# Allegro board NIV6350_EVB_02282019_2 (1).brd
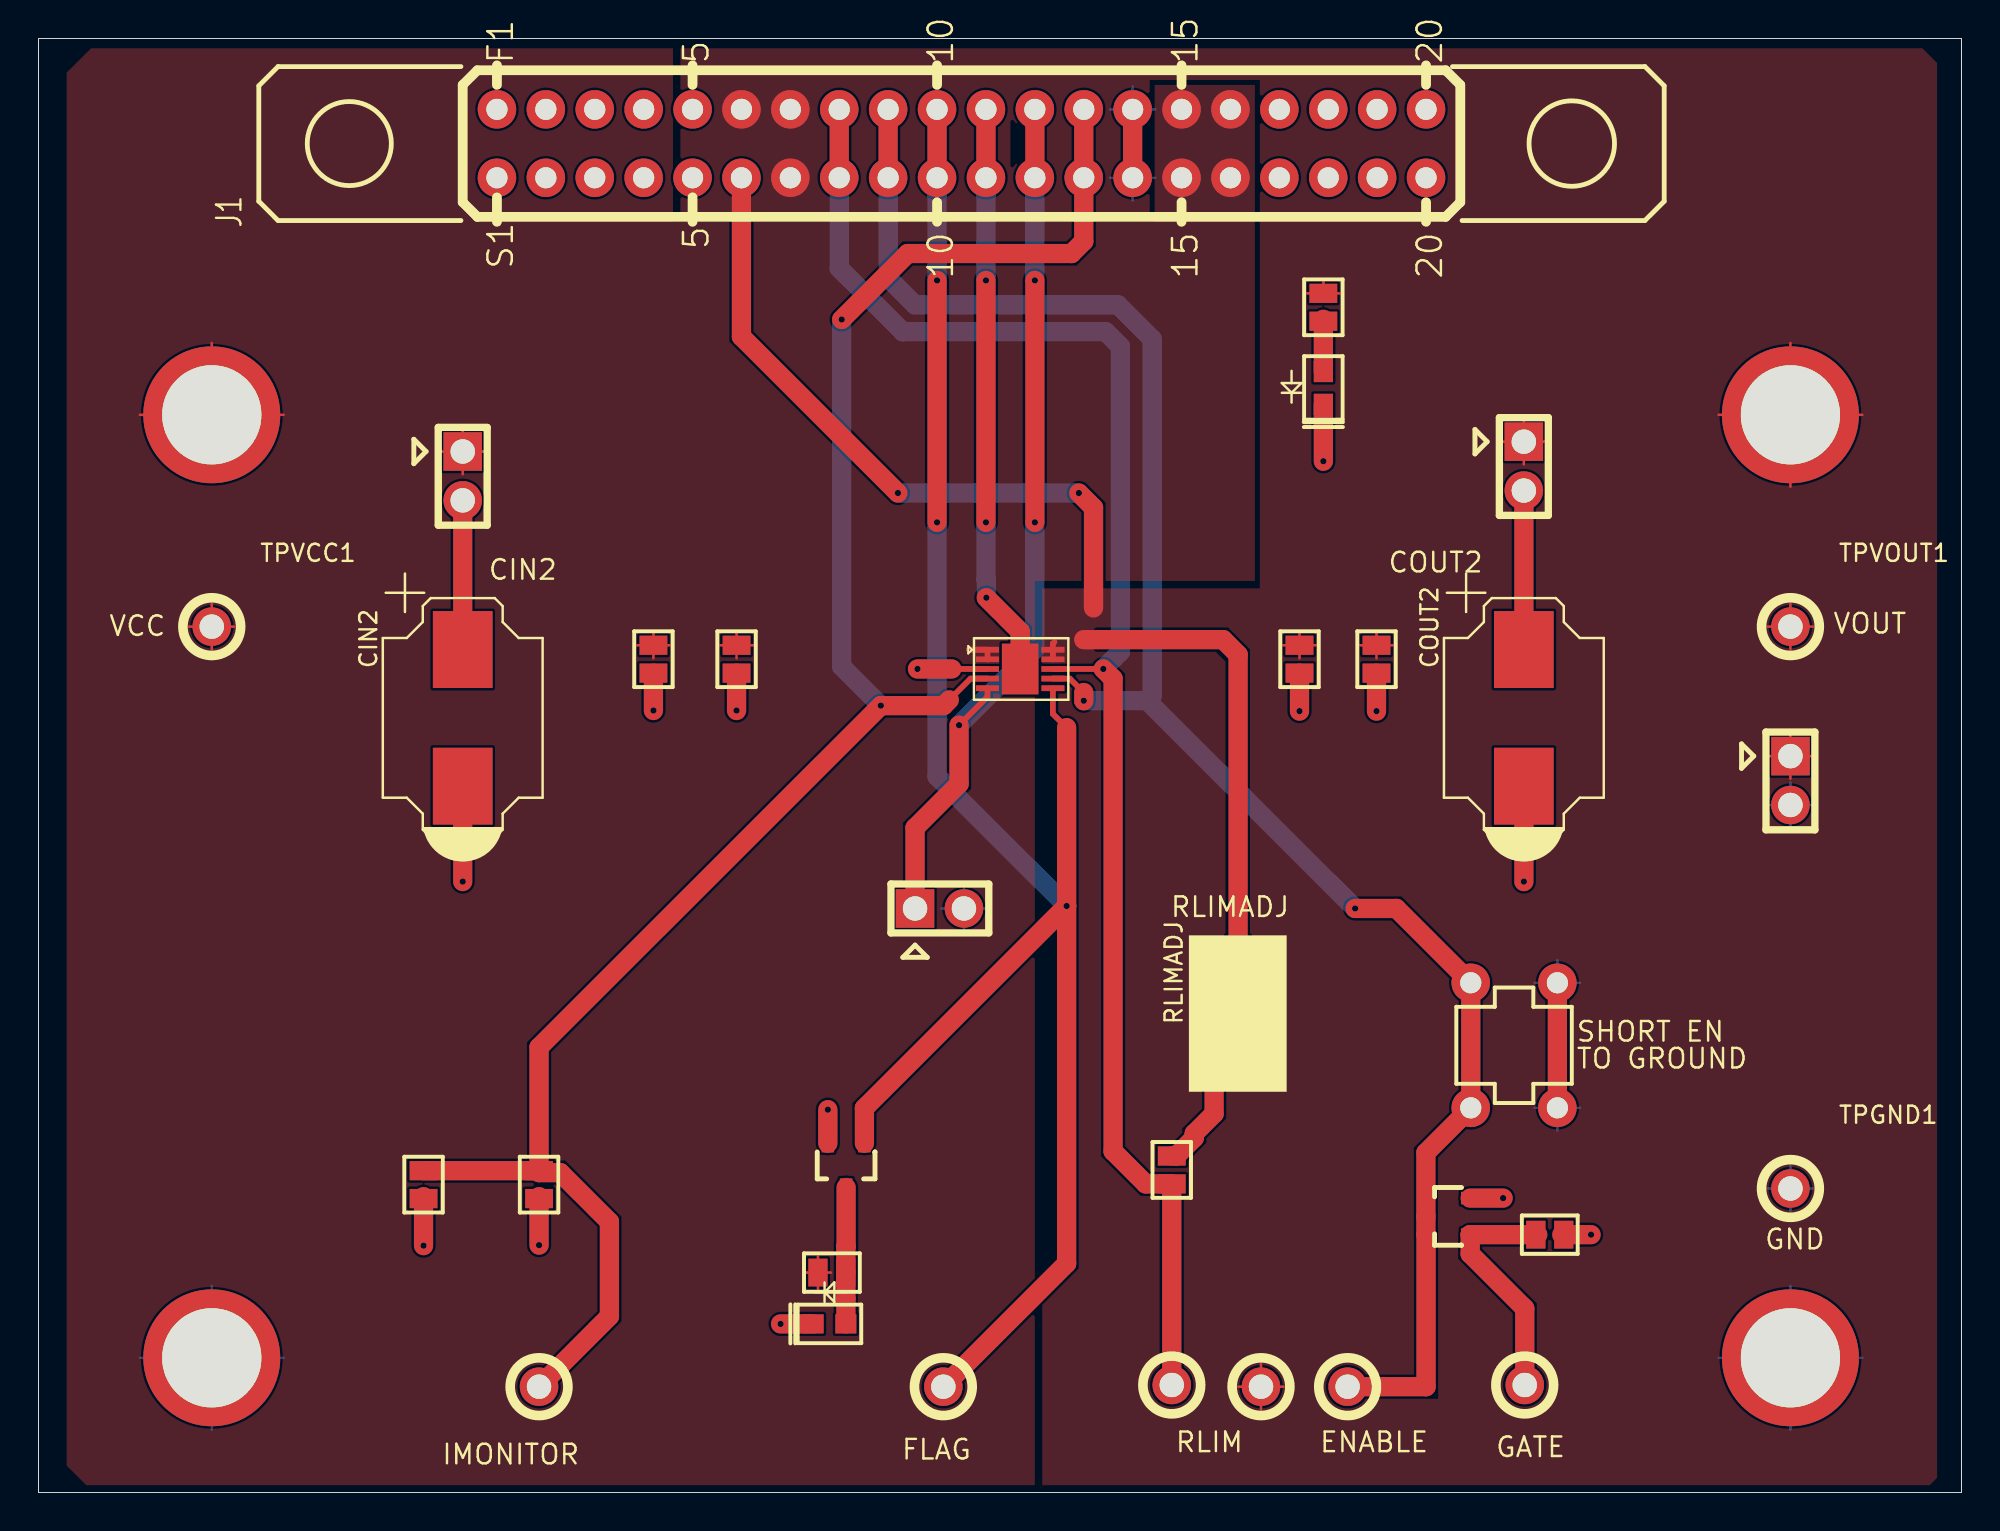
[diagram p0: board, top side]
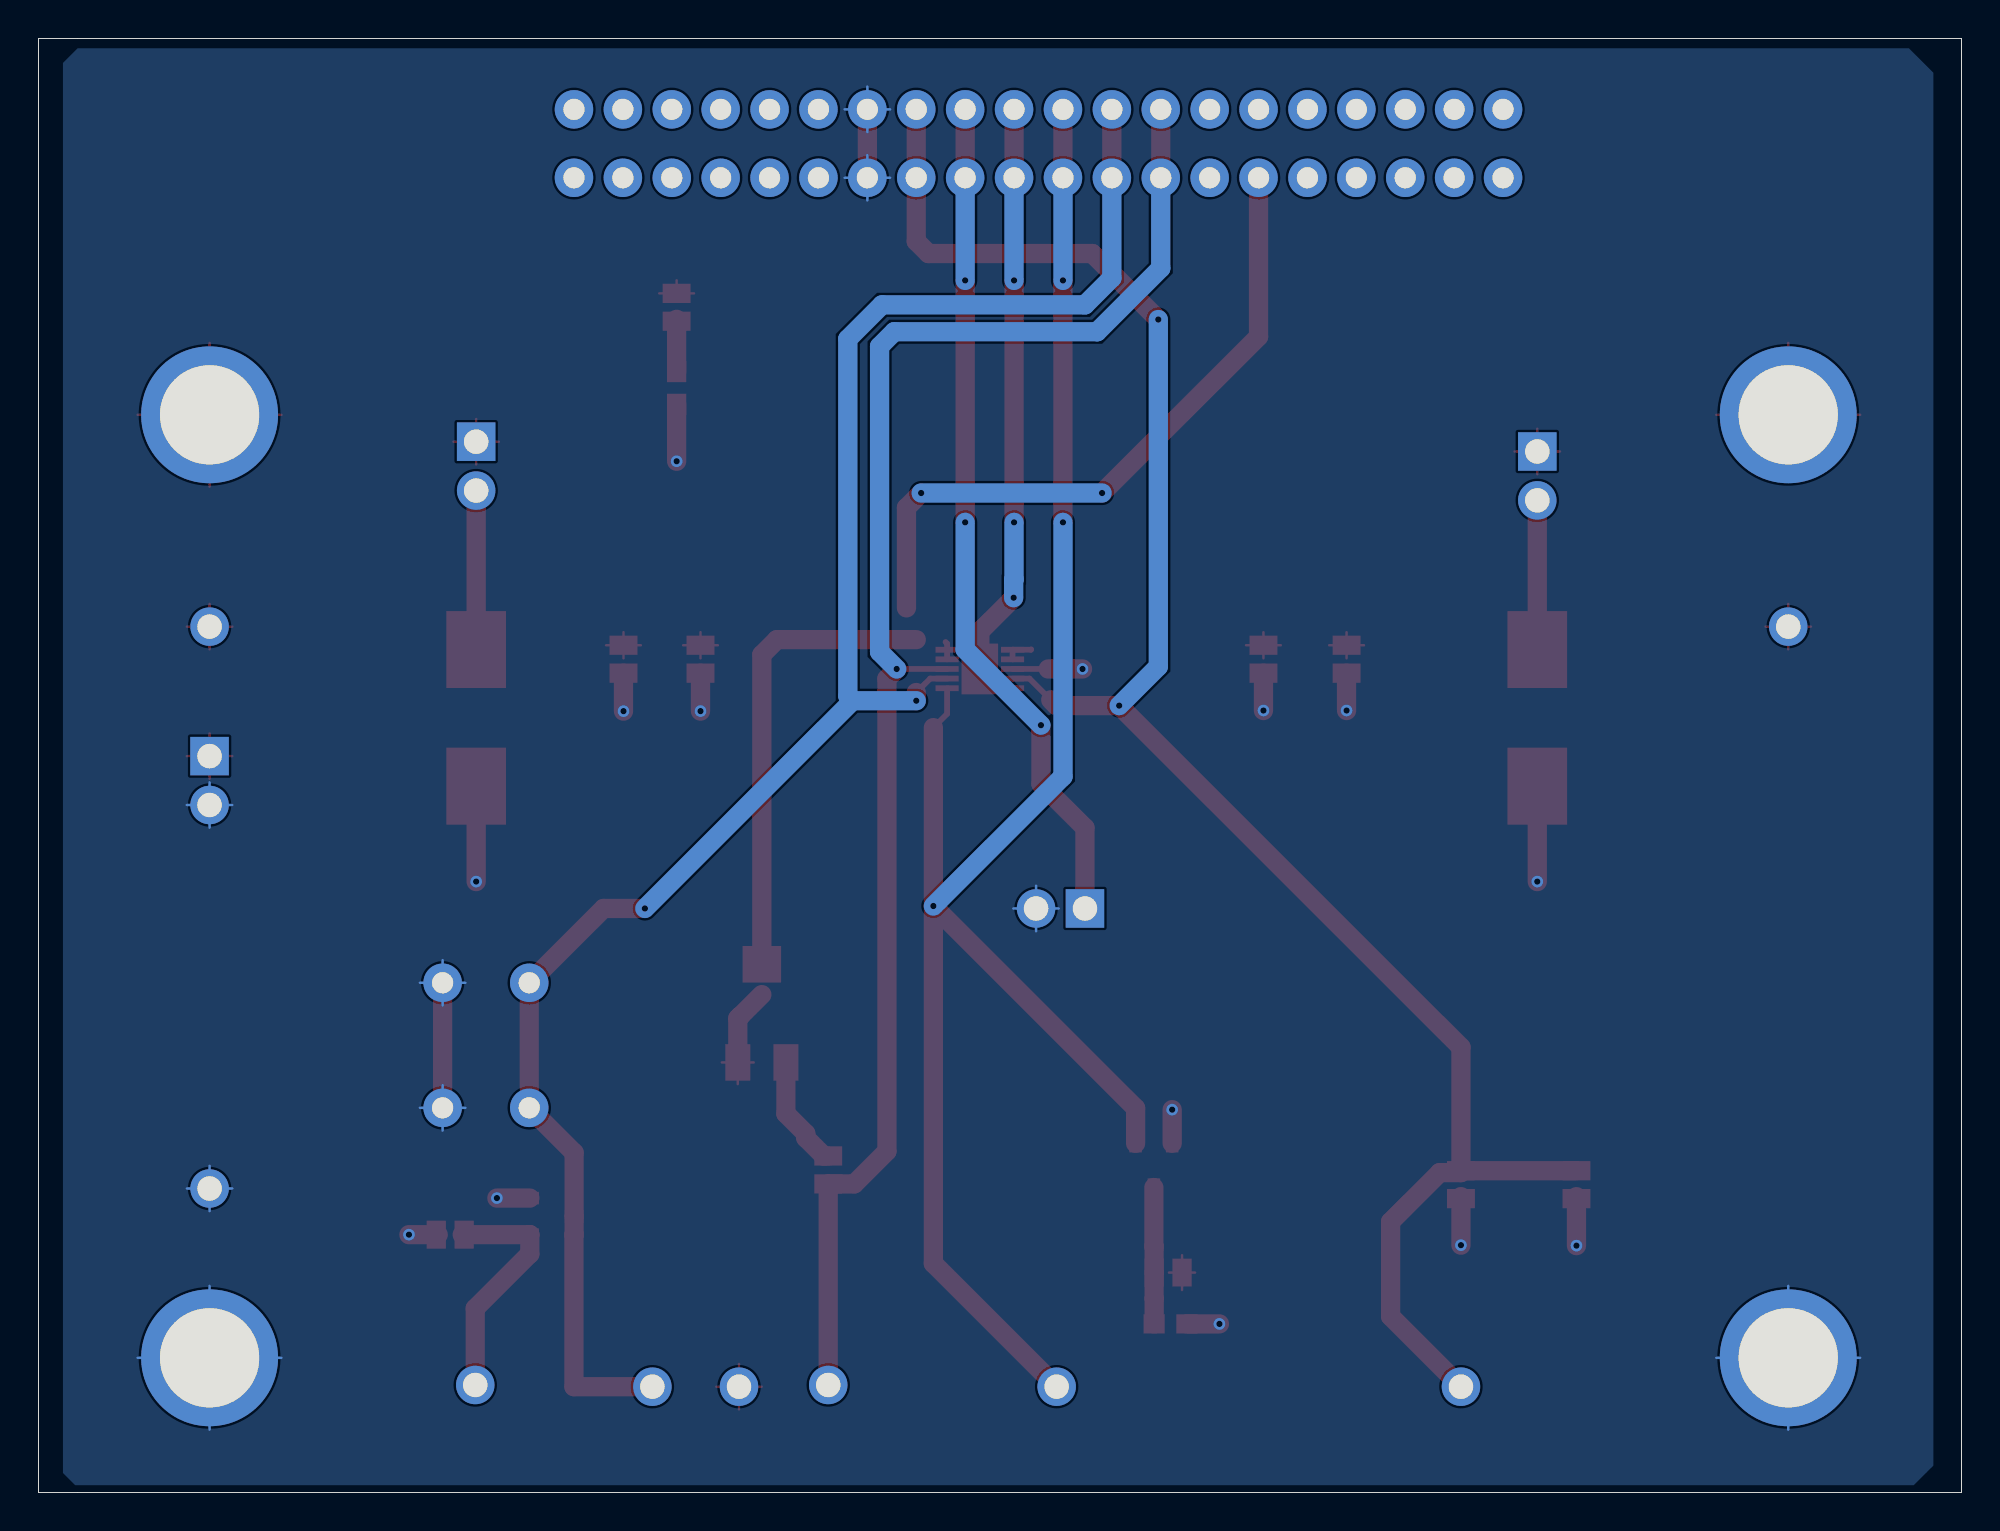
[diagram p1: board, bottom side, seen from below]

Outline 99.89 x 75.56 mm; copper layers: TOP, BOTTOM. Coordinates in mm from the lower left corner of the outline.
Outline path: 0,75.56 99.89,75.56 99.89,0 0,0 0,75.56

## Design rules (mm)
constraint set DEFAULT: min track width 0.127

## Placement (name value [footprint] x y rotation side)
CIMON  1 uF/50V  [0805]  26 16 270 top
CIN1  1uF/50V  [0805]  36.26 43.31 270 top
CIN2  56u/35V  [CAP_SMD_8P3X8P3]  22.04 40.26 90 top
COUT1  1uF/50V  [0805]  65.5 43.31 270 top
COUT2  56uF/35V  [CAP_SMD_8P3X8P3]  77.15 40.26 90 top
D1  LED0603-YELLOW  [LED0603]  41.09 8.76 180 top
EN_SW  PB-SW  [SW-TAC-SPST]  76.64 23.24 90 top
J1  CON40  [ABC20DRT]  47.94 70.1 90 top
J2  TP  [TP-HOOK]  68 5.5 0 top
J3  TP  [TP-HOOK]  47 5.5 0 top
J5  TP  [TP-HOOK]  77.2 5.59 0 top
J_VC_SEL  HDR2  [HEADER-2]  46.8 30.35 0 top
JCIN2  HDR-2  [HEADER-2]  22.04 52.83 270 top
JCOUT2  HDR-2  [HEADER-2]  77.15 53.34 270 top
JGND1  BANANA JACK  [BANANA_VIA]  9 7 0 top
JGND2  BANANA JACK  [BANANA_VIA]  91 7 0 top
JOUTPUTSHORT  HDR-2  [HEADER-2]  91 37 270 top
JVCC1  BANANA JACK  [BANANA_VIA]  9 56.01 0 top
JVOUT1  BANANA JACK  [BANANA_VIA]  91 56.01 0 top
LEDOUT  LED0603-GREEN  [LED0603]  66.74 57.4 270 top
M1  2N7002KT1G  [SOT-23]  73.22 14.35 180 top
M2  2N7002KT1G  [SOT-23]  41.95 17 270 top
R1  10K  [0805]  78.5 13.4 0 top
R2  RFaultLED  [0805]  41.21 11.43 0 top
RIMON  1k  [0805]  20 16 270 top
RLEDOUT  10K  [0805]  66.74 61.59 270 top
RLIMADJ  100  [3214X_TRIM_POT]  63.56 22.35 90 top
RLIMMIN  1  [0805]  58.87 16.76 270 top
TPGND1  -  [TP-HOOK]  91 15.8 0 top
TPIMON  -  [TP-HOOK]  26 5.5 0 top
TPRLIM1  -  [TP-HOOK]  58.87 5.59 0 top
TPRLIM2  -  [TP-HOOK]  63.5 5.5 0 top
TPVCC1  -  [TP-HOOK]  9 45 0 top
TPVOUT1  -  [TP-HOOK]  91 45 0 top
U1  NIV6350  [DFN-10-3X3-05MM]  50.99 42.8 270 top
ZDIN  DIODE ZENER  [0805]  31.94 43.31 270 top
ZDOUT  DIODE ZENER  [0805]  69.5 43.31 270 top

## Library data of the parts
CIMON CIN1 COUT1 = CAP NP
CIN2 COUT2 = CAP
D1 LEDOUT = LED_0
EN_SW = PUSH-BUTTON-SW_2: Tolerance: TOL; User Part Number: PN
J1 = CON40_0
J2 J3 J5 TPGND1 TPIMON TPRLIM1 TPRLIM2 TPVCC1 TPVOUT1 = TP-HOOK
J_VC_SEL = HEADER 2_0: User Part Number: PN; Tolerance: TOL
JCIN2 JCOUT2 JOUTPUTSHORT = HEADER 2_1: User Part Number: PN; Tolerance: TOL
JGND1 JGND2 JVCC1 JVOUT1 = Banana Conn
M1 M2 = MMDF4N01HD/ON_1: User Part Number: PN; Tolerance: TOL
R1 R2 RIMON RLEDOUT RLIMMIN = RESISTOR
RLIMADJ = POT/SM
U1 = NIV6350
ZDIN ZDOUT = DIODE ZENER

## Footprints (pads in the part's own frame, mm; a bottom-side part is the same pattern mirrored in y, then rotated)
0805
  rect 1x1.45 smd: 1(-0.725,0) 2(0.725,0)
3214X_TRIM_POT
  rect 1.9x1.3 smd: 1(0,0) 3(0,2.5)
  rect 1.9x2 smd: 2(5.1,1.25)
ABC20DRT
  round 2 hole 1.1: 1(-1.778,24.13) 2(1.778,24.13) 3(-1.778,21.59) 4(1.778,21.59) 5(-1.778,19.05) 6(1.778,19.05) 7(-1.778,16.51) 8(1.778,16.51) 9(-1.778,13.97) 10(1.778,13.97) 11(-1.778,11.43) 12(1.778,11.43) 13(-1.778,8.89) 14(1.778,8.89) 15(-1.778,6.35) 16(1.778,6.35) 17(-1.778,3.81) 18(1.778,3.81) 19(-1.778,1.27) 20(1.778,1.27) 21(-1.778,-1.27) 22(1.778,-1.27) 23(-1.778,-3.81) 24(1.778,-3.81) 25(-1.778,-6.35) 26(1.778,-6.35) 27(-1.778,-8.89) 28(1.778,-8.89) 29(-1.778,-11.43) 30(1.778,-11.43) 31(-1.778,-13.97) 32(1.778,-13.97) 33(-1.778,-16.51) 34(1.778,-16.51) 35(-1.778,-19.05) 36(1.778,-19.05) 37(-1.778,-21.59) 38(1.778,-21.59) 39(-1.778,-24.13) 40(1.778,-24.13)
BANANA_VIA
  round 7.112 hole 5.156: 1(0,0)
CAP_SMD_8P3X8P3
  rect 4x3.1 smd: 1(3.55,0) 2(-3.55,0)
DFN-10-3X3-05MM
  rect 0.3x1.2 smd: 1(-1,-1.7) 2(-0.5,-1.7) 3(0,-1.7) 4(0.5,-1.7) 5(1,-1.7) 6(1,1.7) 7(0.5,1.7) 8(0,1.7) 9(-0.5,1.7) 10(-1,1.7)
  rect 2.64x1.9 smd: 11(0,0)
HEADER-2
  rect 2x2 hole 1.27: 1(-1.27,0)
  round 2 hole 1.27: 2(1.27,0)
LED0603
  rect 1.1x1 smd: 1(0.851,0) 2(-0.851,0)
SOT-23
  rect 0.95x0.65 smd: 1(-1.15,0.95) 2(-1.15,-0.95) 3(1.15,0)
SW-TAC-SPST
  round 2 hole 1.1: 1(-3.25,-2.25) 2(3.25,-2.25) 3(-3.25,2.25) 4(3.25,2.25)
TP-HOOK
  round 2 hole 1.27: 1(0,0)

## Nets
GND: CIMON.2 CIN1.2 CIN2.2 COUT1.2 COUT2.2 D1.1(CATHODE) EN_SW.1 EN_SW.2 J1.27 J1.28 J_VC_SEL.2 JGND1.1 JGND2.1 JOUTPUTSHORT.2 LEDOUT.1(CATHODE) M1.2(S) M2.2(S) R1.2 RIMON.2 TPGND1.1 U1.3 ZDIN.2 ZDOUT.2
VCC: CIN1.1 J1.29 J1.30 J1.31 J1.32 JCIN2.1 JVCC1.1 R2.1 TPVCC1.1 U1.1 U1.2 ZDIN.1(CATHODE)
EN: EN_SW.3 EN_SW.4 J1.17 J1.18 J2.1 M1.3 U1.7
FLAG: J1.19 J1.20 J3.1 M2.1 U1.6
ILIM: J1.15 J1.16 RLIMMIN.2 TPRLIM1.1 U1.8
IMON: CIMON.1 J1.25 J1.26 RIMON.1 TPIMON.1 U1.4
TPAD: J1.21 J1.22 U1.11
VC_SEL: J1.23 J1.24 J_VC_SEL.1 U1.5(VC_SEL)
VSRC: COUT1.1 J1.11 J1.12 J1.13 J1.14 JCOUT2.1 JOUTPUTSHORT.1 JVOUT1.1 RLEDOUT.1 RLIMADJ.1 RLIMADJ.2(WIPER) TPRLIM2.1 TPVOUT1.1 U1.9 U1.10 ZDOUT.1(CATHODE)
N12391538: LEDOUT.2 RLEDOUT.2
N12393096: RLIMADJ.3 RLIMMIN.1
N14404692: COUT2.1 JCOUT2.2
N14450563: D1.2 M2.3 R2.2
N14454265: J5.1 M1.1 R1.1
N144197141: CIN2.1 JCIN2.2

Pads without a net: J1 1 2 3 4 5 6 7 8 9 10 33 34 35 36 37 38 39 40

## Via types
v1: diameter 0.61, hole 0.33, TOP to BOTTOM, 30 vias

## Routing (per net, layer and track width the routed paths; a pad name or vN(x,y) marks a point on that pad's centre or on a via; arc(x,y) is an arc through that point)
GND: length 109
  TOP w0.3: 47.44,42.8 U1.3
  TOP w1: 26,15.38 CIMON.2 v1(26,12.86) ; EN_SW.2 EN_SW.1 ; LEDOUT.1 v1(66.74,53.59) ; v1(80.64,13.4) R1.2 79.12,13.4 ; v1(20,12.83) RIMON.2 20,15.38 ; ZDIN.2 v1(31.94,40.64) ; D1.1 v1(38.55,8.76) ; CIN1.2 v1(36.26,40.64) ; ZDOUT.2 v1(69.5,40.61) ; J1.27 J1.28 ; COUT2.2 v1(77.15,31.75) ; M2.2 v1(41,19.9) ; CIN2.2 v1(22.04,31.75) ; M1.2 v1(76.08,15.3) ; v1(45.66,42.8) 47.44,42.8 ; COUT1.2 v1(65.5,40.61)
  BOTTOM w0.127: J1.27 58.01,68.33 ; J1.27 56.83,69.5 ; J1.27 56.83,67.15 ; J1.27 55.66,68.33 ; JOUTPUTSHORT.2 92.18,35.73 ; JOUTPUTSHORT.2 89.82,35.73 ; JOUTPUTSHORT.2 91,36.91 ; JOUTPUTSHORT.2 91,34.55 ; 78.89,18.81 EN_SW.1 ; EN_SW.1 77.72,19.99 ; EN_SW.1 78.89,21.17 ; EN_SW.1 80.07,19.99 ; 91,14.62 TPGND1.1 ; TPGND1.1 89.82,15.8 ; TPGND1.1 91,16.98 ; TPGND1.1 92.18,15.8 ; 87.27,7 JGND2.1 ; JGND2.1 91,3.27 ; JGND2.1 91,10.73 ; JGND2.1 94.73,7 ; 78.89,25.31 EN_SW.2 ; EN_SW.2 77.72,26.49 ; EN_SW.2 80.07,26.49 ; EN_SW.2 78.89,27.67 ; 46.89,30.35 J_VC_SEL.2 ; J_VC_SEL.2 49.25,30.35 ; J_VC_SEL.2 48.07,29.18 ; J_VC_SEL.2 48.07,31.53 ; J1.28 58.01,71.88 ; J1.28 56.83,70.7 ; J1.28 56.83,73.06 ; J1.28 55.66,71.88 ; 5.27,7 JGND1.1 ; JGND1.1 12.73,7 ; JGND1.1 9,10.73 ; JGND1.1 9,3.27
VCC: length 33.6
  TOP w0.127: CIN1.1 36.26,44.71 ; CIN1.1 37.16,44.03 ; CIN1.1 36.26,43.35 ; CIN1.1 35.36,44.03 ; R2.1 40.49,12.33 ; R2.1 41.17,11.43 ; R2.1 39.81,11.43 ; R2.1 40.49,10.53 ; TPVCC1.1 10.18,45 ; TPVCC1.1 7.82,45 ; TPVCC1.1 9,43.82 ; TPVCC1.1 9,46.18 ; JCIN2.1 22.04,55.28 ; JCIN2.1 22.04,52.92 ; JCIN2.1 20.86,54.1 ; JCIN2.1 23.21,54.1 ; ZDIN.1 31.94,44.71 ; ZDIN.1 32.84,44.03 ; ZDIN.1 31.94,43.35 ; ZDIN.1 31.04,44.03 ; JVCC1.1 9,59.74 ; JVCC1.1 9,54 ; JVCC1.1 5.27,56.01 ; JVCC1.1 12.73,56.01
  TOP w0.3: U1.2 U1.1 48.34,43.8 48.32,43.81
EN: length 97.2
  TOP w0.3: 54.29,41.57 53.57,42.3 U1.7
  TOP w1: v1(68.39,30.35) 70.53,30.35 EN_SW.4 EN_SW.3 72.07,17.66 M1.3 72.07,13.4 72.07,13.39 72.07,5.5 J2.1 ; J1.17 J1.18 ; v1(54.29,41.15) 54.29,41.57
  BOTTOM w1: 57.59,41.15 v1(68.39,30.35) ; 57.59,41.15 v1(54.29,41.15) ; 57.59,41.15 57.85,41.4 57.85,59.94 56.07,61.72 45.53,61.72 44.13,63.12 J1.17
FLAG: length 100.1
  TOP w0.3: 53.4,39.75 52.69,40.46 U1.6
  TOP w1: J3.1 53.4,11.9 v1(53.4,30.48) ; v1(53.4,30.48) 42.9,19.98 M2.1 ; v1(53.4,30.48) 53.4,39.75 ; v1(46.67,62.99) v1(46.67,50.42) ; J1.19 J1.20
  BOTTOM w1: v1(46.67,50.42) 46.67,37.21 v1(53.4,30.48) ; J1.19 v1(46.67,62.99)
ILIM: length 83.8
  TOP w0.3: v1(55.31,42.8) U1.8
  TOP w1: TPRLIM1.1 RLIMMIN.2 57.51,16.04 55.82,17.73 55.82,42.29 v1(55.31,42.8) ; J1.15 J1.16
  BOTTOM w1: v1(55.31,42.8) 56.2,43.69 56.2,59.56 55.44,60.33 44.9,60.33 41.59,63.63 J1.15
IMON: length 100.6
  TOP w0.3: U1.4 48.41,42.3 47.31,41.19
  TOP w1: v1(41.72,60.96) 45.15,64.39 53.66,64.39 54.29,65.02 J1.25 J1.26 ; CIMON.1 RIMON.1 ; CIMON.1 26,23.14 v1(43.75,40.89) 47.01,40.89 47.31,41.19 ; CIMON.1 26,16.62 27.1,16.62 29.66,14.07 29.66,9.15 TPIMON.1
  BOTTOM w1: v1(43.75,40.89) 41.72,42.93 v1(41.72,60.96)
TPAD: length 29.8
  TOP w1: J1.21 J1.22 ; v1(49.23,46.5) 50.99,44.75 U1.11 ; v1(49.21,62.99) v1(49.21,50.42)
  BOTTOM w1: v1(49.23,46.5) 49.23,47.43 49.21,47.46 v1(49.21,50.42) ; J1.21 v1(49.21,62.99)
VC_SEL: length 46.6
  TOP w0.3: v1(47.82,39.88) 49.29,41.35 U1.5
  TOP w1: v1(51.75,62.99) v1(51.75,50.42) ; v1(47.82,39.88) 47.82,36.83 45.53,34.54 J_VC_SEL.1 ; J1.23 J1.24
  BOTTOM w1: v1(51.75,50.42) 51.75,43.81 v1(47.82,39.88) ; J1.23 v1(51.75,62.99)
VSRC: length 110.2
  TOP w0.127: 63.56,21.22 RLIMADJ.1 ; RLIMADJ.1 62.74,22.35 ; RLIMADJ.1 64.39,22.35 ; JCOUT2.1 77.15,55.79 ; JCOUT2.1 78.33,54.61 ; JCOUT2.1 77.15,53.43 ; JCOUT2.1 75.97,54.61 ; TPRLIM2.1 64.68,5.5 ; TPRLIM2.1 63.5,6.68 ; TPRLIM2.1 62.32,5.5 ; TPRLIM2.1 63.5,4.32 ; 87.27,56.01 JVOUT1.1 ; JVOUT1.1 91,59.74 ; JVOUT1.1 91,52.27 ; JVOUT1.1 94.73,56.01 ; ZDOUT.1 69.5,44.71 ; ZDOUT.1 69.5,43.35 ; ZDOUT.1 70.4,44.03 ; ZDOUT.1 68.6,44.03 ; 65.84,62.32 RLEDOUT.1 ; RLEDOUT.1 66.74,63 ; RLEDOUT.1 67.64,62.32 ; JOUTPUTSHORT.1 91,39.45 ; JOUTPUTSHORT.1 91,37.09 ; JOUTPUTSHORT.1 89.82,38.27 ; JOUTPUTSHORT.1 92.18,38.27 ; 91,43.82 TPVOUT1.1 ; TPVOUT1.1 92.18,45 ; TPVOUT1.1 89.82,45 ; TPVOUT1.1 91,46.18 ; COUT1.1 65.5,44.71 ; COUT1.1 65.5,43.35 ; COUT1.1 66.4,44.03 ; COUT1.1 64.6,44.03
  TOP w0.3: 52.77,44.2 52.69,44.12 U1.10 U1.9
  TOP w1: RLIMADJ.1 63.56,24.64 63.44,24.77 63.42,24.77 62.31,25.88 ; v1(44.64,51.94) 36.51,60.07 J1.11 ; 54.29,44.32 61.53,44.32 62.31,43.54 RLIMADJ.2 ; 54.8,45.97 54.8,51.18 v1(54.04,51.94)
  BOTTOM w1: v1(44.64,51.94) v1(54.04,51.94)
N12391538: length 2.7
  TOP w1: 66.74,60.97 RLEDOUT.2 LEDOUT.2
N12393096: length 5.9
  TOP w1: RLIMADJ.3 61.06,19.69 60.03,18.66 60.03,18.43 59.09,17.49 RLIMMIN.1
N14404692: length 8.3
  TOP w1: COUT2.1 JCOUT2.2
N14450563: length 7.1
  TOP w1: M2.3 41.95,12.8 41.94,12.78 R2.2 41.94,10.08 41.94,10.08 D1.2
N14454265: length 12.5
  TOP w1: 77.88,13.4 R1.1 74.37,13.4 74.37,13.4 74.37,12.4 77.2,9.57 J5.1
N144197141: length 7.8
  TOP w1: JCIN2.2 CIN2.1

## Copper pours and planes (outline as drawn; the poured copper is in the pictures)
GND on BOTTOM: 2.73,75.06 1.46,73.79 1.46,1.4 2.48,0.38 97.98,0.38 98.62,1.02 98.62,74.3 97.85,75.06
VCC on TOP: 49.88,44.2 49.88,43.13 49.75,43 48.1,43 47.97,43.13 47.97,44.2
VCC on TOP: 2.48,0.38 1.46,1.4 1.46,73.79 2.73,75.06 32.96,75.06 32.96,66.04 57.98,66.04 57.98,73.15 63.18,73.15 63.18,47.37 51.75,47.37 51.75,0.38 ; 1 cut-out
VSRC on TOP: 57.72,73.41 57.72,66.42 33.47,66.42 33.34,66.55 33.34,75.06 97.85,75.06 98.62,74.3 98.62,0.76 98.23,0.38 52.13,0.38 52.13,46.99 63.44,46.99 63.44,73.41 ; 5 cut-outs
VSRC on TOP: 52.41,43.08 52.41,44.61 52.54,44.74 53.17,44.74 53.3,44.61 53.3,43.34 53.04,43.08

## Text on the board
Ref Des/Silkscreen Top: VCC | IMONITOR | CIN2 | FLAG | RLIMADJ | RLIM | ENABLE | COUT2 | GATE | SHORT EN | TO GROUND | GND | VOUT
XSECTION_CHART: *  SURFACE - AIR 0 MM | L1 TOP CONDUCTOR - COPPER 0.03048 MM | *  DIELECTRIC - FR-4 1.54 MM | L2 BOTTOM CONDUCTOR - COPPER 0.03048 MM | DESIGN CROSS SECTION CHART | ___________________________ | TOTAL THICKNESS 1.60096 MM | 1-2
BODY_CENTER: FIGURE | FINISHED_SIZE | 0.3302 | 1.1 | 1.27 | 5.1562 | DRILL CHART: TOP to BOTTOM | ALL UNITS ARE IN MILLIMETERS | PLATED | QTY | 30 | 44 | 17 | 4 | 95 | TOTAL HOLES:
